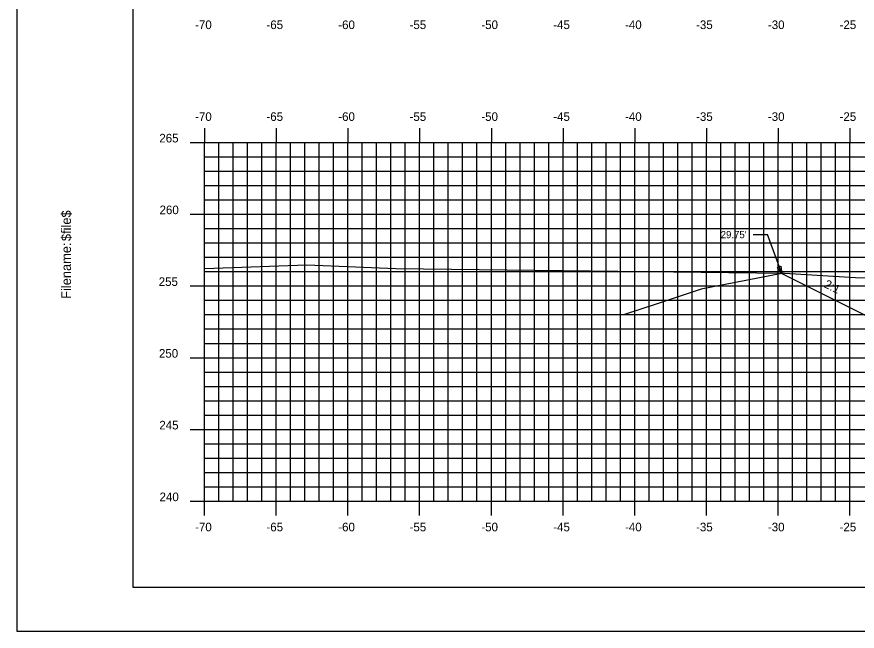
# Model space of a CAD drawing. Extents: x 1160718 to 1173142, y 616002 to 617630.
# Drawn here: x 1170544.6 to 1170603.2, y 616613.9 to 616656.7 of the extents above; entities that cross this region are included whole.
import ezdxf

# ---------------------------------------------------------------- set-up
doc = ezdxf.new("R2010")
doc.units = 0
for name, color, linetype in [('ANNOTATION', 7, 'Continuous'), ('BORDER', 7, 'Continuous'), ('D_Roadway_Centerline', 7, 'Continuous'), ('D_Roadway_Edge_Pavement', 7, 'Continuous'), ('H_V ANNOTATION', 7, 'Continuous'), ('MAJOR', 7, 'Continuous'), ('MINOR', 7, 'Continuous'), ('PLOT BOUNDARY', 7, 'Continuous'), ('S_Roadway_Centerline', 7, 'Continuous')]:
    doc.layers.add(name, color=color, linetype=linetype)

msp = doc.modelspace()

# ---------------------------------------------------------------- linework, layer by layer
at = {"layer": 'ANNOTATION'}
for p, q in [((1170595.93, 616641.505), (1170596.93, 616641.505)), ((1170597.916, 616638.794), (1170596.93, 616641.505)), ((1170597.841, 616638.831), (1170603.786, 616635.859)), ((1170557.664, 616635.928), (1170586.946, 616635.928))]:
    msp.add_line(p, q, dxfattribs=at)
msp.add_lwpolyline([(1170597.862, 616639.306), (1170597.916, 616638.794), (1170597.627, 616639.221)], close=True, dxfattribs=at)
at = {"layer": 'BORDER'}
for p, q in [((1170552.664, 616721.928), (1170552.664, 616616.928)), ((1170552.664, 616616.928), (1170712.664, 616616.928))]:
    msp.add_line(p, q, dxfattribs=at)
at = {"layer": 'D_Roadway_Centerline'}
msp.add_lwpolyline([(1170597.916, 616638.794), (1170603.786, 616635.859), (1170608.664, 616638.297)], dxfattribs=at)
at = {"layer": 'D_Roadway_Edge_Pavement'}
msp.add_lwpolyline([(1170597.916, 616638.794), (1170592.306, 616637.713), (1170591.038, 616637.291), (1170589.303, 616636.713), (1170588.026, 616636.288), (1170586.946, 616635.928)], dxfattribs=at)
at = {"layer": 'MAJOR'}
for p, q in [((1170557.664, 616648.93), (1170557.664, 616647.928)), ((1170562.664, 616648.93), (1170562.664, 616647.928)), ((1170567.664, 616648.93), (1170567.664, 616647.928)), ((1170572.664, 616648.93), (1170572.664, 616647.928)), ((1170577.664, 616648.93), (1170577.664, 616647.928)), ((1170582.664, 616648.93), (1170582.664, 616647.928)), ((1170587.664, 616648.93), (1170587.664, 616647.928)), ((1170592.664, 616648.93), (1170592.664, 616647.928)), ((1170597.664, 616648.93), (1170597.664, 616647.928)), ((1170602.664, 616648.93), (1170602.664, 616647.928)), ((1170556.662, 616647.928), (1170557.664, 616647.928)), ((1170557.664, 616647.928), (1170697.664, 616647.928)), ((1170557.664, 616622.928), (1170557.664, 616647.928)), ((1170557.664, 616622.928), (1170557.664, 616647.928)), ((1170557.664, 616647.928), (1170697.664, 616647.928)), ((1170562.664, 616622.928), (1170562.664, 616647.928)), ((1170567.664, 616622.928), (1170567.664, 616647.928)), ((1170572.664, 616622.928), (1170572.664, 616647.928)), ((1170577.664, 616622.928), (1170577.664, 616647.928)), ((1170582.664, 616622.928), (1170582.664, 616647.928)), ((1170587.664, 616622.928), (1170587.664, 616647.928)), ((1170592.664, 616622.928), (1170592.664, 616647.928)), ((1170597.664, 616622.928), (1170597.664, 616647.928)), ((1170602.664, 616622.928), (1170602.664, 616647.928)), ((1170556.662, 616642.928), (1170557.664, 616642.928)), ((1170557.664, 616642.928), (1170697.664, 616642.928)), ((1170556.662, 616637.928), (1170557.664, 616637.928)), ((1170557.664, 616637.928), (1170697.664, 616637.928)), ((1170556.662, 616632.928), (1170557.664, 616632.928)), ((1170557.664, 616632.928), (1170697.664, 616632.928)), ((1170556.662, 616627.928), (1170557.664, 616627.928)), ((1170557.664, 616627.928), (1170697.664, 616627.928)), ((1170556.662, 616622.928), (1170557.664, 616622.928)), ((1170557.664, 616622.928), (1170697.664, 616622.928)), ((1170557.664, 616622.928), (1170697.664, 616622.928)), ((1170557.664, 616621.926), (1170557.664, 616622.928)), ((1170562.664, 616621.926), (1170562.664, 616622.928)), ((1170567.664, 616621.926), (1170567.664, 616622.928)), ((1170572.664, 616621.926), (1170572.664, 616622.928)), ((1170577.664, 616621.926), (1170577.664, 616622.928)), ((1170582.664, 616621.926), (1170582.664, 616622.928)), ((1170587.664, 616621.926), (1170587.664, 616622.928)), ((1170592.664, 616621.926), (1170592.664, 616622.928)), ((1170597.664, 616621.926), (1170597.664, 616622.928)), ((1170602.664, 616621.926), (1170602.664, 616622.928))]:
    msp.add_line(p, q, dxfattribs=at)
at = {"layer": 'MINOR'}
for p, q in [((1170558.664, 616622.928), (1170558.664, 616647.928)), ((1170559.664, 616622.928), (1170559.664, 616647.928)), ((1170560.664, 616622.928), (1170560.664, 616647.928)), ((1170561.664, 616622.928), (1170561.664, 616647.928)), ((1170563.664, 616622.928), (1170563.664, 616647.928)), ((1170564.664, 616622.928), (1170564.664, 616647.928)), ((1170565.664, 616622.928), (1170565.664, 616647.928)), ((1170566.664, 616622.928), (1170566.664, 616647.928)), ((1170568.664, 616622.928), (1170568.664, 616647.928)), ((1170569.664, 616622.928), (1170569.664, 616647.928)), ((1170570.664, 616622.928), (1170570.664, 616647.928)), ((1170571.664, 616622.928), (1170571.664, 616647.928)), ((1170573.664, 616622.928), (1170573.664, 616647.928)), ((1170574.664, 616622.928), (1170574.664, 616647.928)), ((1170575.664, 616622.928), (1170575.664, 616647.928)), ((1170576.664, 616622.928), (1170576.664, 616647.928)), ((1170578.664, 616622.928), (1170578.664, 616647.928)), ((1170579.664, 616622.928), (1170579.664, 616647.928)), ((1170580.664, 616622.928), (1170580.664, 616647.928)), ((1170581.664, 616622.928), (1170581.664, 616647.928)), ((1170583.664, 616622.928), (1170583.664, 616647.928)), ((1170584.664, 616622.928), (1170584.664, 616647.928)), ((1170585.664, 616622.928), (1170585.664, 616647.928)), ((1170586.664, 616622.928), (1170586.664, 616647.928)), ((1170588.664, 616622.928), (1170588.664, 616647.928)), ((1170589.664, 616622.928), (1170589.664, 616647.928)), ((1170590.664, 616622.928), (1170590.664, 616647.928)), ((1170591.664, 616622.928), (1170591.664, 616647.928)), ((1170593.664, 616622.928), (1170593.664, 616647.928)), ((1170594.664, 616622.928), (1170594.664, 616647.928)), ((1170595.664, 616622.928), (1170595.664, 616647.928)), ((1170596.664, 616622.928), (1170596.664, 616647.928)), ((1170598.664, 616622.928), (1170598.664, 616647.928)), ((1170599.664, 616622.928), (1170599.664, 616647.928)), ((1170600.664, 616622.928), (1170600.664, 616647.928)), ((1170601.664, 616622.928), (1170601.664, 616647.928)), ((1170557.664, 616646.928), (1170697.664, 616646.928)), ((1170557.664, 616646.928), (1170558.666, 616646.928)), ((1170557.664, 616645.928), (1170697.664, 616645.928)), ((1170557.664, 616645.928), (1170558.666, 616645.928)), ((1170557.664, 616644.928), (1170697.664, 616644.928)), ((1170557.664, 616644.928), (1170558.666, 616644.928)), ((1170557.664, 616643.928), (1170697.664, 616643.928)), ((1170557.664, 616643.928), (1170558.666, 616643.928)), ((1170557.664, 616641.928), (1170697.664, 616641.928)), ((1170557.664, 616641.928), (1170558.666, 616641.928)), ((1170557.664, 616640.928), (1170697.664, 616640.928)), ((1170557.664, 616640.928), (1170558.666, 616640.928)), ((1170557.664, 616639.928), (1170697.664, 616639.928)), ((1170557.664, 616639.928), (1170558.666, 616639.928)), ((1170557.664, 616638.928), (1170697.664, 616638.928)), ((1170557.664, 616638.928), (1170558.666, 616638.928)), ((1170557.664, 616636.928), (1170697.664, 616636.928)), ((1170557.664, 616636.928), (1170558.666, 616636.928)), ((1170557.664, 616635.928), (1170697.664, 616635.928)), ((1170557.664, 616635.928), (1170558.666, 616635.928)), ((1170557.664, 616634.928), (1170697.664, 616634.928)), ((1170557.664, 616634.928), (1170558.666, 616634.928)), ((1170557.664, 616633.928), (1170697.664, 616633.928)), ((1170557.664, 616633.928), (1170558.666, 616633.928)), ((1170557.664, 616631.928), (1170697.664, 616631.928)), ((1170557.664, 616631.928), (1170558.666, 616631.928)), ((1170557.664, 616630.928), (1170697.664, 616630.928)), ((1170557.664, 616630.928), (1170558.666, 616630.928)), ((1170557.664, 616629.928), (1170697.664, 616629.928)), ((1170557.664, 616629.928), (1170558.666, 616629.928)), ((1170557.664, 616628.928), (1170697.664, 616628.928)), ((1170557.664, 616628.928), (1170558.666, 616628.928)), ((1170557.664, 616626.928), (1170697.664, 616626.928)), ((1170557.664, 616626.928), (1170558.666, 616626.928)), ((1170557.664, 616625.928), (1170697.664, 616625.928)), ((1170557.664, 616625.928), (1170558.666, 616625.928)), ((1170557.664, 616624.928), (1170697.664, 616624.928)), ((1170557.664, 616624.928), (1170558.666, 616624.928)), ((1170557.664, 616623.928), (1170697.664, 616623.928)), ((1170557.664, 616623.928), (1170558.666, 616623.928))]:
    msp.add_line(p, q, dxfattribs=at)
at = {"layer": 'PLOT BOUNDARY'}
msp.add_lwpolyline([(1170544.57, 616613.869), (1170714.57, 616613.869), (1170714.57, 616723.869), (1170544.57, 616723.869)], close=True, dxfattribs=at)
at = {"layer": 'S_Roadway_Centerline'}
msp.add_lwpolyline([(1170557.664, 616639.133), (1170564.795, 616639.41), (1170570.998, 616639.147), (1170598.104, 616638.815), (1170603.049, 616638.506), (1170626.043, 616638.184), (1170631.056, 616637.888), (1170648.586, 616637.335), (1170660.236, 616633.74)], dxfattribs=at)

# ---------------------------------------------------------------- texts
at = {"layer": 'ANNOTATION'}
msp.add_text("29.75'", height=0.5, dxfattribs=at).set_placement((1170593.661, 616641.255))
msp.add_text('2:1', height=0.6, rotation=333.43495, dxfattribs=at).set_placement((1170600.818, 616637.861))
at = {"layer": 'BORDER'}
for s, p in [('$file$', (1170548.349, 616641.054)), ('Filename:', (1170548.349, 616637.027))]:
    msp.add_text(s, height=0.6696, rotation=90, dxfattribs=at).set_placement(p)
at = {"layer": 'H_V ANNOTATION'}
for s, p in [('-70', (1170557.005, 616655.828)), ('-65', (1170561.981, 616655.828)), ('-60', (1170566.989, 616655.828)), ('-55', (1170571.96, 616655.828)), ('-50', (1170576.968, 616655.828)), ('-45', (1170581.981, 616655.828)), ('-40', (1170586.989, 616655.828)), ('-35', (1170591.944, 616655.828)), ('-30', (1170596.952, 616655.828)), ('-25', (1170601.949, 616655.828)), ('-70', (1170557.005, 616649.428)), ('-65', (1170561.981, 616649.428)), ('-60', (1170566.989, 616649.428)), ('-55', (1170571.96, 616649.428)), ('-50', (1170576.968, 616649.428)), ('-45', (1170581.981, 616649.428)), ('-40', (1170586.989, 616649.428)), ('-35', (1170591.944, 616649.428)), ('-30', (1170596.952, 616649.428)), ('-25', (1170601.949, 616649.428)), ('265', (1170554.51, 616647.928)), ('260', (1170554.526, 616642.928)), ('255', (1170554.467, 616637.928)), ('250', (1170554.483, 616632.928)), ('245', (1170554.51, 616627.928)), ('240', (1170554.526, 616622.928)), ('-70', (1170557.005, 616620.828)), ('-65', (1170561.981, 616620.828)), ('-60', (1170566.989, 616620.828)), ('-55', (1170571.96, 616620.828)), ('-50', (1170576.968, 616620.828)), ('-45', (1170581.981, 616620.828)), ('-40', (1170586.989, 616620.828)), ('-35', (1170591.944, 616620.828)), ('-30', (1170596.952, 616620.828)), ('-25', (1170601.949, 616620.828))]:
    msp.add_text(s, height=0.6, dxfattribs=at).set_placement(p)

doc.saveas('drawing.dxf')
